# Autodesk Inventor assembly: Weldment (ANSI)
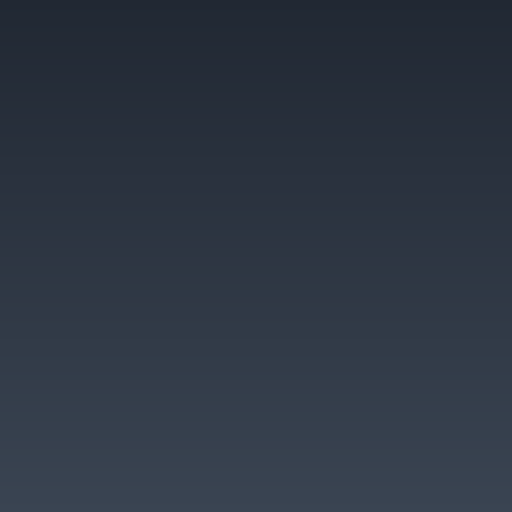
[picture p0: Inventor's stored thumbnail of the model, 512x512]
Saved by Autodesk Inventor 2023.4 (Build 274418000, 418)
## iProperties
Length Units: 11272
Angle Units: 11286
Time Units: 11279
Mass Units: 11290
Length Display Precision: 3
Angle Display Precision: 2
Part Number: Weldment (ANSI)
Document SubType Name: Weldment
Created: 2002-06
Designer: smithga
Part Number: Weldment (in)
Created: 2002-08
Weld Material: Welded Aluminum-6061
Control State: 0
Master: False
Shininess: 64.0
Angle Units: 11279
Time Units: 11290
Mass Units: 11286
Compacted: True
Density: 0.0
Volumn: 0.0
Area: 0.0
PropertySet Name: Model Information
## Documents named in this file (1)
- C:\Users\H4ECDSTG\Documents\_VaultWork\Standards\2024 Template Work Group\Templates\Weldment (in).iam
